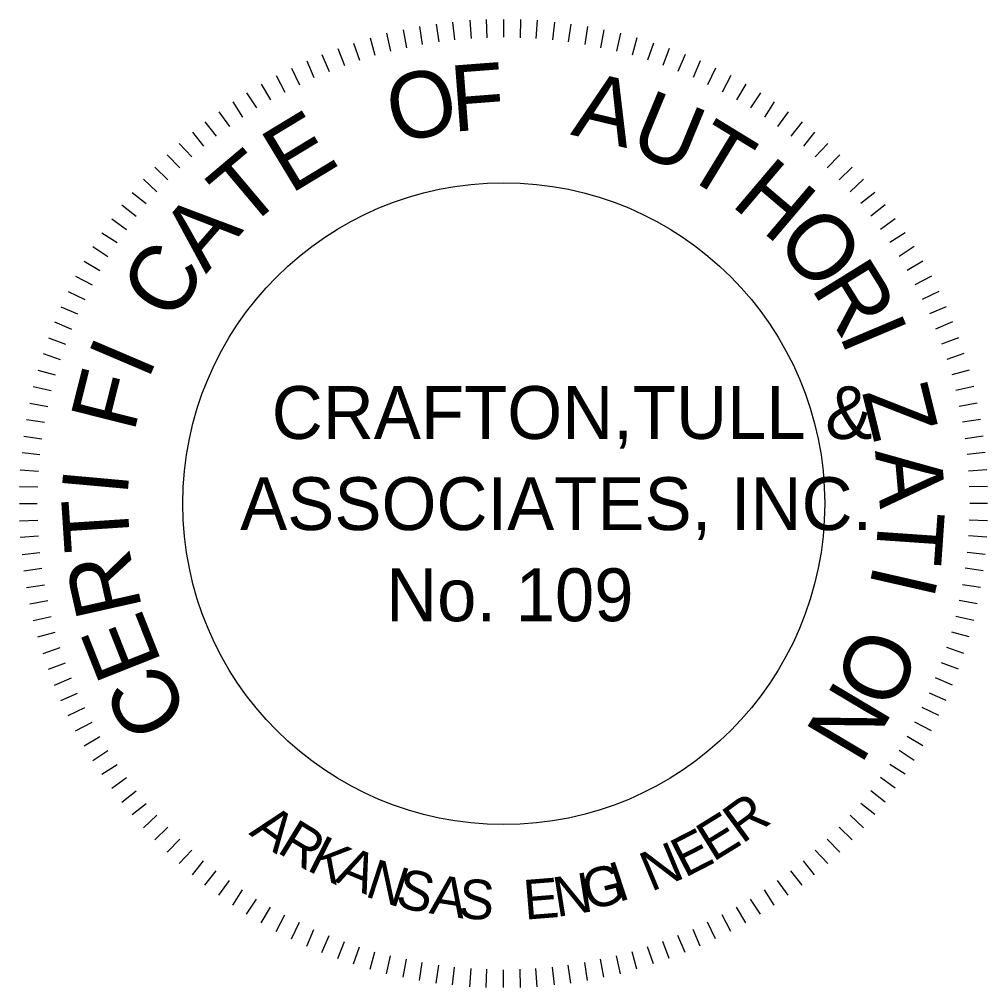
# Model space of a CAD drawing. Extents: x 6028647 to 6035072, y 5366486 to 5368495.
# Drawn here: x 6031045.9 to 6031317.1, y 5366537 to 5366808.2 of the extents above; entities that cross this region are included whole.
import ezdxf

# ---------------------------------------------------------------- set-up
doc = ezdxf.new("R2010")
doc.units = 0
doc.layers.add('R_Border Prem', color=7, linetype='Continuous')

msp = doc.modelspace()

# ---------------------------------------------------------------- linework, layer by layer
at = {"layer": 'R_Border Prem'}
for p, q in [((6031162.65, 5366806.95), (6031163.39, 5366801.96)), ((6031167.28, 5366807.51), (6031167.83, 5366802.51)), ((6031172.09, 5366808.06), (6031172.46, 5366802.88)), ((6031176.71, 5366808.25), (6031176.9, 5366803.07)), ((6031181.52, 5366808.25), (6031181.52, 5366803.25)), ((6031186.33, 5366808.25), (6031186.15, 5366803.07)), ((6031190.96, 5366808.06), (6031190.59, 5366802.88)), ((6031195.77, 5366807.51), (6031195.21, 5366802.51)), ((6031200.39, 5366806.95), (6031199.65, 5366801.96)), ((6031148.78, 5366804.36), (6031149.89, 5366799.37)), ((6031153.4, 5366805.29), (6031154.33, 5366800.29)), ((6031158.03, 5366806.21), (6031158.77, 5366801.22)), ((6031205.02, 5366806.21), (6031204.28, 5366801.22)), ((6031209.64, 5366805.29), (6031208.72, 5366800.29)), ((6031214.27, 5366804.36), (6031213.16, 5366799.37)), ((6031139.53, 5366801.59), (6031141.19, 5366796.78)), ((6031144.15, 5366803.07), (6031145.45, 5366798.26)), ((6031218.89, 5366803.07), (6031217.6, 5366798.26)), ((6031223.52, 5366801.59), (6031221.85, 5366796.78)), ((6031130.65, 5366798.44), (6031132.68, 5366793.63)), ((6031135.09, 5366800.11), (6031136.94, 5366795.3)), ((6031227.96, 5366800.11), (6031226.11, 5366795.3)), ((6031232.4, 5366798.44), (6031230.36, 5366793.63)), ((6031126.39, 5366796.59), (6031128.43, 5366791.97)), ((6031236.65, 5366796.59), (6031234.62, 5366791.97)), ((6031122.14, 5366794.56), (6031124.36, 5366789.93)), ((6031240.91, 5366794.56), (6031238.69, 5366789.93)), ((6031117.88, 5366792.52), (6031120.29, 5366787.9)), ((6031245.16, 5366792.52), (6031242.76, 5366787.9)), ((6031109.56, 5366787.71), (6031112.33, 5366783.46)), ((6031113.63, 5366790.12), (6031116.22, 5366785.68)), ((6031249.42, 5366790.12), (6031246.83, 5366785.68)), ((6031253.49, 5366787.71), (6031250.71, 5366783.46)), ((6031105.67, 5366785.12), (6031108.45, 5366780.87)), ((6031257.37, 5366785.12), (6031254.6, 5366780.87)), ((6031101.79, 5366782.35), (6031104.75, 5366778.28)), ((6031261.26, 5366782.35), (6031258.3, 5366778.28)), ((6031097.9, 5366779.57), (6031101.05, 5366775.5)), ((6031265.14, 5366779.57), (6031262, 5366775.5)), ((6031094.39, 5366776.61), (6031097.53, 5366772.73)), ((6031268.66, 5366776.61), (6031265.51, 5366772.73)), ((6031090.69, 5366773.47), (6031094.2, 5366769.77)), ((6031272.36, 5366773.47), (6031268.84, 5366769.77)), ((6031087.36, 5366770.32), (6031090.87, 5366766.62)), ((6031275.69, 5366770.32), (6031272.17, 5366766.62)), ((6031083.84, 5366766.81), (6031087.54, 5366763.29)), ((6031279.2, 5366766.81), (6031275.5, 5366763.29)), ((6031080.7, 5366763.48), (6031084.4, 5366759.96)), ((6031282.35, 5366763.48), (6031278.65, 5366759.96)), ((6031077.55, 5366759.78), (6031081.44, 5366756.63)), ((6031285.49, 5366759.78), (6031281.61, 5366756.63)), ((6031074.59, 5366756.26), (6031078.66, 5366753.12)), ((6031288.45, 5366756.26), (6031284.38, 5366753.12)), ((6031071.82, 5366752.38), (6031075.89, 5366749.42)), ((6031291.23, 5366752.38), (6031287.16, 5366749.42)), ((6031069.04, 5366748.49), (6031073.3, 5366745.72)), ((6031294, 5366748.49), (6031289.75, 5366745.72)), ((6031066.45, 5366744.61), (6031070.71, 5366741.83)), ((6031296.59, 5366744.61), (6031292.34, 5366741.83)), ((6031064.05, 5366740.54), (6031068.49, 5366737.95)), ((6031299, 5366740.54), (6031294.56, 5366737.95)), ((6031061.64, 5366736.28), (6031066.27, 5366733.88)), ((6031301.4, 5366736.28), (6031296.78, 5366733.88)), ((6031059.61, 5366732.03), (6031064.23, 5366729.81)), ((6031303.44, 5366732.03), (6031298.81, 5366729.81)), ((6031057.57, 5366727.77), (6031062.2, 5366725.74)), ((6031305.47, 5366727.77), (6031300.85, 5366725.74)), ((6031055.72, 5366723.52), (6031060.53, 5366721.48)), ((6031307.32, 5366723.52), (6031302.51, 5366721.48)), ((6031054.06, 5366719.08), (6031058.87, 5366717.23)), ((6031308.99, 5366719.08), (6031304.18, 5366717.23)), ((6031052.58, 5366714.64), (6031057.39, 5366712.97)), ((6031310.47, 5366714.64), (6031305.66, 5366712.97)), ((6031051.1, 5366710.01), (6031055.91, 5366708.72)), ((6031311.95, 5366710.01), (6031307.14, 5366708.72)), ((6031049.8, 5366705.39), (6031054.8, 5366704.28)), ((6031313.24, 5366705.39), (6031308.25, 5366704.28)), ((6031048.88, 5366700.76), (6031053.87, 5366699.84)), ((6031314.17, 5366700.76), (6031309.17, 5366699.84)), ((6031047.95, 5366696.14), (6031052.95, 5366695.4)), ((6031315.09, 5366696.14), (6031310.1, 5366695.4)), ((6031047.21, 5366691.51), (6031052.21, 5366690.77)), ((6031315.83, 5366691.51), (6031310.84, 5366690.77)), ((6031046.66, 5366686.89), (6031051.65, 5366686.33)), ((6031316.39, 5366686.89), (6031311.39, 5366686.33)), ((6031046.1, 5366682.08), (6031051.28, 5366681.71)), ((6031316.94, 5366682.08), (6031311.76, 5366681.71)), ((6031045.92, 5366677.45), (6031051.1, 5366677.27)), ((6031317.13, 5366677.45), (6031311.95, 5366677.27)), ((6031045.92, 5366672.64), (6031050.91, 5366672.64)), ((6031317.13, 5366672.64), (6031312.13, 5366672.64)), ((6031045.92, 5366667.83), (6031051.1, 5366668.02)), ((6031317.13, 5366667.83), (6031311.95, 5366668.02)), ((6031046.1, 5366663.21), (6031051.28, 5366663.58)), ((6031316.94, 5366663.21), (6031311.76, 5366663.58)), ((6031046.66, 5366658.4), (6031051.65, 5366658.95)), ((6031316.39, 5366658.4), (6031311.39, 5366658.95)), ((6031047.21, 5366653.77), (6031052.21, 5366654.51)), ((6031315.83, 5366653.77), (6031310.84, 5366654.51)), ((6031047.95, 5366649.15), (6031052.95, 5366649.89)), ((6031315.09, 5366649.15), (6031310.1, 5366649.89)), ((6031048.88, 5366644.52), (6031053.87, 5366645.45)), ((6031314.17, 5366644.52), (6031309.17, 5366645.45)), ((6031049.8, 5366639.9), (6031054.8, 5366641.01)), ((6031313.24, 5366639.9), (6031308.25, 5366641.01)), ((6031051.1, 5366635.27), (6031055.91, 5366636.57)), ((6031311.95, 5366635.27), (6031307.14, 5366636.57)), ((6031052.58, 5366630.65), (6031057.39, 5366632.31)), ((6031310.47, 5366630.65), (6031305.66, 5366632.31)), ((6031054.06, 5366626.21), (6031058.87, 5366628.06)), ((6031308.99, 5366626.21), (6031304.18, 5366628.06)), ((6031055.72, 5366621.77), (6031060.53, 5366623.8)), ((6031307.32, 5366621.77), (6031302.51, 5366623.8)), ((6031057.57, 5366617.51), (6031062.2, 5366619.55)), ((6031305.47, 5366617.51), (6031300.85, 5366619.55)), ((6031059.61, 5366613.26), (6031064.23, 5366615.48)), ((6031303.44, 5366613.26), (6031298.81, 5366615.48)), ((6031061.64, 5366609), (6031066.27, 5366611.41)), ((6031301.4, 5366609), (6031296.78, 5366611.41)), ((6031064.05, 5366604.75), (6031068.49, 5366607.34)), ((6031299, 5366604.75), (6031294.56, 5366607.34)), ((6031066.45, 5366600.68), (6031070.71, 5366603.45)), ((6031296.59, 5366600.68), (6031292.34, 5366603.45)), ((6031069.04, 5366596.79), (6031073.3, 5366599.57)), ((6031294, 5366596.79), (6031289.75, 5366599.57)), ((6031071.82, 5366592.91), (6031075.89, 5366595.87)), ((6031291.23, 5366592.91), (6031287.16, 5366595.87)), ((6031074.59, 5366589.02), (6031078.66, 5366592.17)), ((6031288.45, 5366589.02), (6031284.38, 5366592.17)), ((6031077.55, 5366585.51), (6031081.44, 5366588.65)), ((6031285.49, 5366585.51), (6031281.61, 5366588.65)), ((6031080.7, 5366581.81), (6031084.4, 5366585.32)), ((6031282.35, 5366581.81), (6031278.65, 5366585.32)), ((6031083.84, 5366578.48), (6031087.54, 5366581.99)), ((6031279.2, 5366578.48), (6031275.5, 5366581.99)), ((6031087.36, 5366574.96), (6031090.87, 5366578.66)), ((6031275.69, 5366574.96), (6031272.17, 5366578.66)), ((6031090.69, 5366571.82), (6031094.2, 5366575.52)), ((6031272.36, 5366571.82), (6031268.84, 5366575.52)), ((6031094.39, 5366568.67), (6031097.53, 5366572.56)), ((6031268.66, 5366568.67), (6031265.51, 5366572.56)), ((6031097.9, 5366565.71), (6031101.05, 5366569.78)), ((6031265.14, 5366565.71), (6031262, 5366569.78)), ((6031101.79, 5366562.94), (6031104.75, 5366567.01)), ((6031261.26, 5366562.94), (6031258.3, 5366567.01)), ((6031105.67, 5366560.16), (6031108.45, 5366564.42)), ((6031257.37, 5366560.16), (6031254.6, 5366564.42)), ((6031109.56, 5366557.57), (6031112.33, 5366561.83)), ((6031253.49, 5366557.57), (6031250.71, 5366561.83)), ((6031113.63, 5366555.17), (6031116.22, 5366559.61)), ((6031117.88, 5366552.76), (6031120.29, 5366557.39)), ((6031245.16, 5366552.76), (6031242.76, 5366557.39)), ((6031249.42, 5366555.17), (6031246.83, 5366559.61)), ((6031122.14, 5366550.73), (6031124.36, 5366555.35)), ((6031240.91, 5366550.73), (6031238.69, 5366555.35)), ((6031126.39, 5366548.69), (6031128.43, 5366553.32)), ((6031130.65, 5366546.84), (6031132.68, 5366551.65)), ((6031232.4, 5366546.84), (6031230.36, 5366551.65)), ((6031236.65, 5366548.69), (6031234.62, 5366553.32)), ((6031135.09, 5366545.18), (6031136.94, 5366549.99)), ((6031227.96, 5366545.18), (6031226.11, 5366549.99)), ((6031139.53, 5366543.7), (6031141.19, 5366548.51)), ((6031144.15, 5366542.22), (6031145.45, 5366547.03)), ((6031218.89, 5366542.22), (6031217.6, 5366547.03)), ((6031223.52, 5366543.7), (6031221.85, 5366548.51)), ((6031148.78, 5366540.92), (6031149.89, 5366545.92)), ((6031153.4, 5366540), (6031154.33, 5366544.99)), ((6031158.03, 5366539.07), (6031158.77, 5366544.07)), ((6031205.02, 5366539.07), (6031204.28, 5366544.07)), ((6031209.64, 5366540), (6031208.72, 5366544.99)), ((6031214.27, 5366540.92), (6031213.16, 5366545.92)), ((6031162.65, 5366538.33), (6031163.39, 5366543.33)), ((6031167.28, 5366537.78), (6031167.83, 5366542.77)), ((6031172.09, 5366537.22), (6031172.46, 5366542.4)), ((6031176.71, 5366537.04), (6031176.9, 5366542.22)), ((6031181.52, 5366537.04), (6031181.52, 5366542.03)), ((6031186.33, 5366537.04), (6031186.15, 5366542.22)), ((6031190.96, 5366537.22), (6031190.59, 5366542.4)), ((6031195.77, 5366537.78), (6031195.21, 5366542.77)), ((6031200.39, 5366538.33), (6031199.65, 5366543.33))]:
    msp.add_line(p, q, dxfattribs=at)
msp.add_circle((6031181.6, 5366672.6), 89.89, dxfattribs=at)

# ---------------------------------------------------------------- texts
for s, height, rotation, p in [('F', 18.5, 4.3732, (6031167.36, 5366776.75)), ('O', 18.5, 13.3113, (6031151.26, 5366773.24)), ('A', 18.5, 346.4969, (6031200.1, 5366776.01)), ('U', 18.5, 337.5588, (6031216.01, 5366771.76)), ('E', 18.5, 31.1876, (6031121.85, 5366759.18)), ('T', 18.5, 328.6206, (6031231, 5366765.1)), ('T', 18.5, 40.1257, (6031109.27, 5366749)), ('H', 18.5, 319.6825, (6031244.87, 5366756.4)), ('A', 18.5, 49.0639, (6031098.17, 5366736.79)), ('O', 18.5, 310.7444, (6031257.08, 5366745.67)), ('C', 18.5, 58.002, (6031089.1, 5366722.92)), ('R', 18.5, 301.8062, (6031267.44, 5366733.09)), ('I', 18.5, 292.8681, (6031275.4, 5366719.96)), ('I', 18.5, 66.9402, (6031081.89, 5366706.82)), ('F', 18.5, 75.8783, (6031078, 5366692.21)), ('Z', 18.5, 283.9299, (6031281.87, 5366703.86)), ('A', 18.5, 274.9918, (6031285.57, 5366687.4)), ('I', 18.5, 84.8164, (6031076.15, 5366674.45)), ('T', 18.5, 93.7546, (6031077.08, 5366659.65)), ('T', 18.5, 266.0537, (6031286.68, 5366671.12)), ('R', 18.5, 102.6927, (6031080.41, 5366643.18)), ('I', 18.5, 257.1155, (6031285.39, 5366656.13)), ('E', 18.5, 111.6308, (6031085.96, 5366628.01)), ('O', 18.5, 248.1774, (6031281.13, 5366639.11)), ('C', 18.5, 120.569, (6031094.1, 5366613.77)), ('N', 18.5, 239.2393, (6031274.84, 5366623.94)), ('R', 11.1, 36.1806, (6031248.39, 5366577.14)), ('A', 11.1, 324.001, (6031110.01, 5366580.1)), ('E', 11.1, 31.6694, (6031240.25, 5366572.14)), ('R', 11.1, 328.5123, (6031117.78, 5366575.1)), ('E', 11.1, 27.1582, (6031232.29, 5366567.7)), ('K', 11.1, 333.0235, (6031126.1, 5366570.11)), ('N', 11.1, 22.647, (6031222.86, 5366563.82)), ('A', 11.1, 337.5347, (6031134.06, 5366566.78)), ('N', 11.1, 342.0459, (6031142.38, 5366562.71)), ('G', 11.1, 13.6245, (6031205.1, 5366558.64)), ('I', 11.1, 18.1357, (6031213.61, 5366560.86)), ('S', 11.1, 346.5572, (6031150.89, 5366559.93)), ('A', 11.1, 351.0684, (6031160.51, 5366557.9)), ('N', 11.1, 9.1133, (6031196.4, 5366556.79)), ('S', 11.1, 355.5796, (6031168.65, 5366556.6)), ('E', 11.1, 4.6021, (6031187.52, 5366556.05))]:
    msp.add_text(s, height=height, rotation=rotation, dxfattribs=at).set_placement(p)
for s, height, p in [('CRAFTON,TULL &', 14.7996, (6031116.61, 5366690.73)), ('ASSOCIATES, INC.', 14.7996, (6031107.75, 5366665.2)), ('No. 109', 14.8, (6031148.63, 5366639.67))]:
    msp.add_text(s, height=height, dxfattribs=at).set_placement(p)

doc.saveas('drawing.dxf')
